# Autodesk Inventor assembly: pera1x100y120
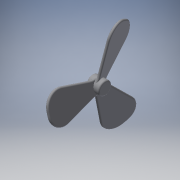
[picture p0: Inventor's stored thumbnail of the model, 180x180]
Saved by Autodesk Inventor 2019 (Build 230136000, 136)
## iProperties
Created: 2020-08
Part Number: pera1x100y120
Material: 一般
Document SubType Name: Assembly
Designer: kikut
Author: kikut
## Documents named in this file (2)
- F:\openFOAM\bathrobo\bathrobo03.2\laminar\oversetmeshpera1\CAD\pera1x100y120.iam
- F:\openFOAM\bathrobo\bathrobo03.2\laminar\oversetmeshpera1\CAD\pera01.ipt
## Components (1 placed, 1 different names)
1. pera01:1 — メイト:1, メイト:2
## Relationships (2: Mate 2)
- メイト:1 [Mate]: pera01:1
- メイト:2 [Mate]: pera01:1
